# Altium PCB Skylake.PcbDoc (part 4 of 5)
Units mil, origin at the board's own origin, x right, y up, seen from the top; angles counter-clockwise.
Board outline 4000 x 4000 mil, 8 copper layers (TOP LAYER, GND1#2, SIG1#3, SIG2#4, GND2#5, SIG3#6, GND3#7, BOTTOM LAYER), stack 132.6 mil thick; 343 components, 142 nets, 972 pads, 752 vias.
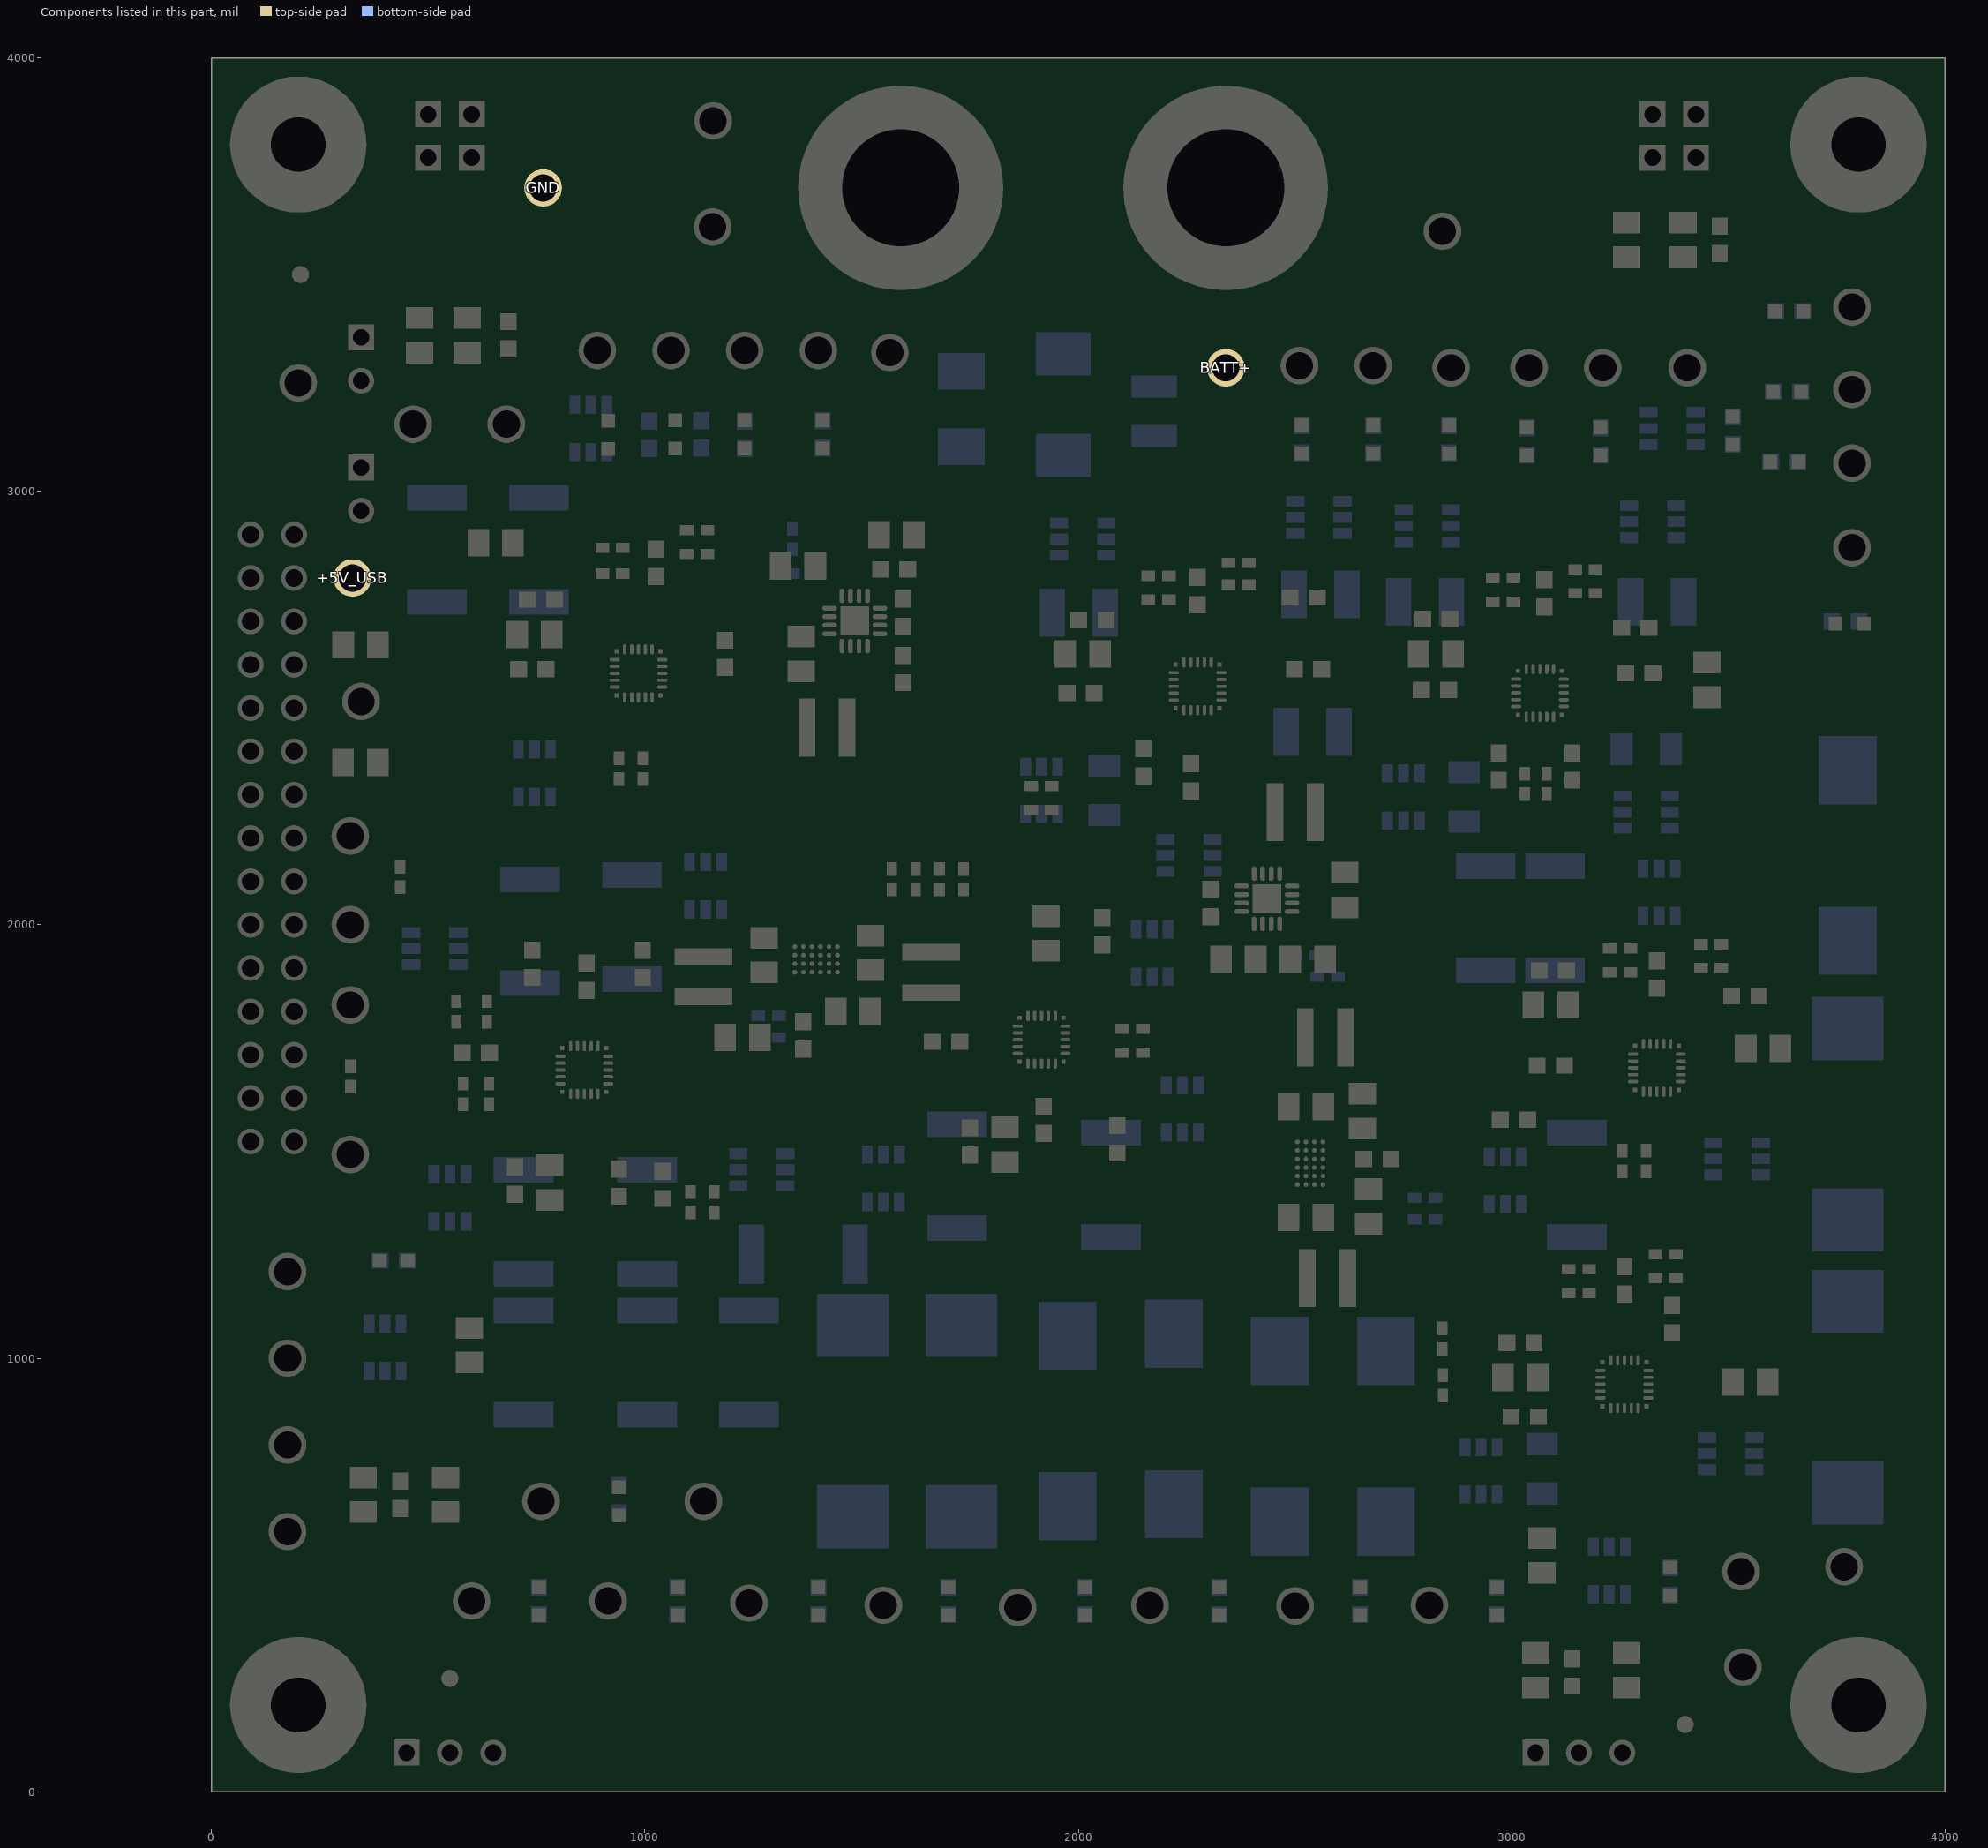
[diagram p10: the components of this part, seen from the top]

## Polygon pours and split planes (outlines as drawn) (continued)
V2(3.3V) on TOP LAYER "Top Layer-No Net" (solid, pour order 239): 832.79,1523.35 832.79,1571.37 847.04,1585.62 876.71,1585.62 888.36,1573.97 888.36,1528.73 877.38,1517.75 838.39,1517.75
V2(3.3V) on TOP LAYER "Top Layer-No Net" (solid, pour order 240): 833,1757.33 833,1805.35 844.85,1817.2 879.32,1817.2 888.57,1807.95 888.57,1762.71 871.39,1745.53 844.8,1745.53
V4(1.00V) on TOP LAYER "Top Layer-No Net" (solid, pour order 242): 1074.32,2605.96 1122.34,2605.96 1132.04,2596.26 1134.19,2594.11 1134.19,2571.71 1134.19,2559.64 1127.73,2553.18 1124.94,2550.39 1090.26,2550.39 1079.7,2550.39 1071.95,2558.14 1068.72,2561.37 1068.72,2588.3 1068.72,2600.36 1074.1,2605.74
GND on TOP LAYER "Top Layer-No Net" (solid, pour order 228): 643.03,2908.98 643.03,2830.71 637.29,2824.97 635.47,2823.16 593.77,2823.16 559.62,2823.16 549.64,2833.13 548.43,2834.34 548.43,2868.19 548.43,2900.82 557.81,2910.19 563.55,2915.93 617.04,2915.93 635.78,2915.93 642.42,2909.28
GND on TOP LAYER "Top Layer-No Net" (solid, pour order 223): 18 vertices, not listed, extent 551.02,924.21 633.29,1015.22
GND on TOP LAYER "Top Layer-No Net" (solid, pour order 222): 18 vertices, not listed, extent 3028.49,438.19 3110.46,530.16
BATT+ on TOP LAYER "Top Layer-No Net" (solid, pour order 269): 17 vertices, not listed, extent 3416.96,2462.19 3488.05,2552.6
BATT+ on TOP LAYER "Top Layer-No Net" (solid, pour order 272): 18 vertices, not listed, extent 3002.52,558.98 3106.08,618.59
BATT+ on TOP LAYER "Top Layer-No Net" (solid, pour order 275): 553.94,1126.76 626.13,1126.76 631.85,1121.04 632.14,1120.75 632.14,1085.09 632.14,1049.98 627,1044.84 626.99,1044.85 568.78,1044.85 555.07,1044.85 548.23,1051.69 547.37,1052.55 547.37,1097.07 547.37,1120.76 553.94,1127.33
BATT+ on TOP LAYER "Top Layer-No Net" (solid, pour order 277): 721.77,2936.69 721.77,2856.99 714.76,2850.93 669.71,2850.93 665,2855 665,2931.98 675.37,2940.93 715.24,2940.93 721.84,2935.24
+5V_USB on TOP LAYER "Top Layer-No Net" (solid, pour order 294): 267.52,2608.49 267.52,2699.62 276.85,2708.95 279.96,2712.06 308.26,2712.06 326.22,2712.06 332.09,2706.19 335.19,2703.09 335.19,2670.63 335.19,2612.96 330.02,2607.79 326.91,2604.68 304.81,2604.68 272.02,2604.68 267.52,2609.18
GND on TOP LAYER "Top Layer-No Net" (solid, pour order 247): 3114.14,2354.14 3157.02,2354.14 3167.2,2343.95 3167.2,2291.84 3161.04,2285.68 3108.95,2285.68 3101.11,2293.52 3101.11,2341.11
V3(3.3V) on TOP LAYER "Top Layer-No Net" (solid, pour order 231): 3479.27,1640.84 3431.25,1640.84 3419.4,1652.69 3419.4,1685.81 3443.79,1710.2 3460.1,1710.2 3484.87,1685.43 3484.87,1646.44
GND on TOP LAYER "Top Layer-No Net" (solid, pour order 256): 3311.06,1947.11 3370.99,1947.11 3377.77,1940.33 3377.77,1900.47 3373.59,1896.29 3321.59,1896.29 3306.36,1911.52 3306.36,1942.41
BATT+ on TOP LAYER "Top Layer-No Net" (solid, pour order 323): 2021.62,2657.78 2092.59,2657.78 2102.19,2648.18 2102.19,2604.85 2089.81,2592.47 2024.47,2592.47 2018.48,2598.46 2018.48,2654.07 2022.48,2658.07
V1.8DX_SENSORS on TOP LAYER "Top Layer-No Net" (solid, pour order 181): 18 vertices, not listed, extent 2039.67,2674.81 2124.66,2753.36
GND on TOP LAYER "Top Layer-No Net" (solid, pour order 303): 2300.95,2330.86 2307.76,2324.05 2307.76,2283.69 2301.44,2277.37 2240.63,2277.37 2232.73,2285.27 2232.73,2322.03 2241.56,2330.86
V1.8M on TOP LAYER "Top Layer-No Net" (solid, pour order 194): 3124.48,2441.33 3172.23,2441.33 3180.81,2432.75 3180.81,2384.42 3172.82,2376.43 3119.21,2376.43 3111.81,2383.83 3111.81,2428.66
V1.8DX_USBSDIO on TOP LAYER "Top Layer-No Net" (solid, pour order 290): 2912.52,2421.33 2913.1,2421.91 2987.65,2421.91 2994.45,2415.11 2994.45,2379.3 2989.34,2374.19 2905.89,2374.19 2895.77,2384.31 2895.77,2404.77 2912.13,2421.13
MODPHY on TOP LAYER "Top Layer-No Net" (solid, pour order 236): 18 vertices, not listed, extent 828.25,2421.24 920.24,2484.65
V3.3M on TOP LAYER "Top Layer-No Net" (solid, pour order 276): 2075.16,1597.69 2128.79,1597.69 2133.76,1592.72 2133.76,1522.86 2128.03,1517.13 2072.09,1517.13 2069.26,1519.96 2069.26,1591.79
GND on TOP LAYER "Top Layer-No Net" (solid, pour order 258): 3047.3,2831.79 3106.52,2831.79 3118.61,2819.7 3118.61,2781.52 3113.71,2776.62 3053.03,2776.62 3044.41,2785.24 3044.41,2828.9
V2(3.3V) on TOP LAYER "Top Layer-No Net" (solid, pour order 237): 1881.76,1601.76 1881.76,1634.58 1902.95,1655.77 1926.54,1655.77 1943.19,1639.12 1943.19,1601.28 1932.21,1590.3 1893.22,1590.3
GND on TOP LAYER "TOP LAYER-No Net 1" (solid, pour order 182): 2249.82,2106 2285.13,2106 2285.13,2067.1 2266,2047.98 2266,1955.53 2311.46,1955.53 2335,1931.99 2344.61,1922.38 2344.61,1852 2265,1852 2262,1855 2232.77,1884.23 2232.77,2088.95
GND on TOP LAYER "Top Layer-No Net" (solid, pour order 195): 34 vertices, not listed, extent 1238.16,1556.47 1576.87,1919.54
GND on TOP LAYER "Top Layer-No Net" (solid, pour order 322): 1996.77,2757.49 2020.44,2733.82 2020.44,2680.38 1994.97,2654.91 1994.97,2399.79 1976.59,2381.41 1873.88,2381.41 1849.29,2406 1849.29,2718.23 1888.55,2757.49
GND on TOP LAYER "Top Layer-No Net" (solid, pour order 191): 1922.01,2280.18 1921.44,2279.61 1921.44,2247.32 1898.98,2224.86 1898.98,2208.79 1905.62,2202.15 1924,2202.15 1931.08,2209.23 1931.08,2224.91 1958.27,2252.1 1958.27,2279.16 1955.81,2281.62 1923.19,2281.62 1921.91,2280.34
GND on TOP LAYER "Top Layer-No Net" (solid, pour order 201): 17 vertices, not listed, extent 3355,3590 3525,3675
GND on TOP LAYER "Top Layer-No Net" (solid, pour order 203): 3220,3685 3320,3685 3335,3670 3335,3610 3320,3595 3220,3595 3205,3610 3205,3670
NetL6_1 on TOP LAYER "Top Layer-No Net" (solid, pour order 184): 1498.99,2659.2 1498.9,2383.33 1489.07,2373.52 1449.64,2373.52 1439.45,2383.68 1439.45,2659.2
GND on TOP LAYER "TOP LAYER-No Net 1" (solid, remove dead copper, pour order 178): 2392.94,2089.53 2493.07,2089.53 2493.07,2067.49 2493.23,2067.22 2390.24,2067.22 2390.24,2086.83
BATT+ on TOP LAYER "Top Layer-No Net" (solid, pour order 198): 40 vertices, not listed, extent 1227.48,1993.09 2631.84,3959.87
BATT+ on BOTTOM LAYER "Top Layer-No Net" (solid, pour order 308): 1383,2892 1445,2892 1460.13,2876.87 1460.13,2814.92 1478.17,2796.88 1478.17,2758.17 1472,2752 1407.7,2752 1370.38,2789.32 1370.38,2879.38
GND on BOTTOM LAYER "Top Layer-No Net" (solid, pour order 314): 2582.59,1877.16 2582.59,1917.43 2593.38,1928.22 2629.29,1928.22 2646.4,1911.11 2646.4,1882.5 2631.23,1867.34 2585,1867.34 2582.59,1869.74 2582.75,1869.91 2582.75,1877.8
V3.3DX_3G4G on BOTTOM LAYER "Top Layer-No Net" (solid, pour order 302): 1663.79,1195.8 1822.55,1195.8 1850,1168.35 1850,996.06 1821.13,967.19 1659.53,967.19 1641,985.72 1641,1174.12 1663.79,1196.91
GND on BOTTOM LAYER "Top Layer-No Net" (solid, pour order 348): 18 vertices, not listed, extent 3024.03,638.88 3151.17,725.24
V3.3DX_3G4G on BOTTOM LAYER "Top Layer-No Net" (solid, pour order 347): 17 vertices, not listed, extent 1953.34,1918.41 2102.16,1999.01
V3.3DX_AUDIO on BOTTOM LAYER "Top Layer-No Net" (solid, pour order 254): 1816.26,1623.41 1816.26,1656.09 1838.84,1678.67 1872.51,1678.67 1882.44,1668.74 1882.44,1617.34 1918.55,1581.23 1918.55,1524.25 1898.62,1504.32 1776.59,1504.32 1766.93,1513.98 1766.93,1574.08
V1.8DX_SSD on BOTTOM LAYER "Top Layer-No Net" (solid, pour order 345): 2350.66,2351.42 2350.65,2351.41 2302.37,2351.41 2282.27,2371.51 2282.27,2391.9 2329.64,2439.27 2355.5,2439.27 2362.65,2432.12 2362.65,2363.11 2350.66,2351.12
V1.8DX_SSD on BOTTOM LAYER "Top Layer-No Net" (solid, pour order 205): 18 vertices, not listed, extent 2280.74,2107.15 2509.45,2528.83
GND on BOTTOM LAYER "Top Layer-No Net" (solid, pour order 343): 3075,1325 3230,1325 3235,1325 3250,1310 3250,1270 3250,1255.51 3239.71,1245.22 3234.49,1240 3155,1240 3080,1240 3070,1250 3070,1305 3070,1320 3075,1325
GND on BOTTOM LAYER "Top Layer-No Net" (solid, pour order 342): 2811.11,1335.99 2857.56,1335.99 2863.98,1329.57 2864.62,1328.93 2864.62,1311.81 2864.62,1298.32 2857.56,1291.26 2849.64,1283.34 2828.45,1283.34 2815.39,1283.34 2811.75,1286.98 2806.19,1292.54 2806.19,1311.59 2806.19,1331.07 2811.11,1335.99
BATT+ on BOTTOM LAYER "Top Layer-No Net" (solid, pour order 341): 2816.04,1413.93 2856.3,1413.93 2861.48,1408.75 2864.54,1405.69 2864.54,1378.14 2864.54,1363.55 2860.77,1359.78 2859.12,1358.13 2834.17,1358.13 2810.87,1358.13 2804.98,1364.02 2804.5,1364.5 2804.5,1377.67 2804.5,1401.92 2816.04,1413.46
V3.3DX_SSD on BOTTOM LAYER "Top Layer-No Net" (solid, pour order 338): 2639.51,1114.55 2793.87,1114.55 2815.52,1092.9 2815.52,941.31 2787.76,913.55 2640.05,913.55 2606.75,946.85 2606.75,1081.79
NetR84_2 on BOTTOM LAYER "Top Layer-No Net" (solid, pour order 305): 3713.14,1412.82 3839.97,1412.82 3862.35,1390.44 3862.35,1066.54 3848.08,1052.27 3700.1,1052.27 3685.13,1067.24 3685.13,1384.81
NetR95_2 on BOTTOM LAYER "Top Layer-No Net" (solid, pour order 330): 18 vertices, not listed, extent 2140,925 2540,1145
GND on BOTTOM LAYER "Top Layer-No Net" (solid, pour order 210): 24 vertices, not listed, extent 1638.97,973.5 2145.42,1481.71
GND on BOTTOM LAYER "Top Layer-No Net" (solid, pour order 326): 26 vertices, not listed, extent 433.69,2465.54 691.23,2804.33
GND on BOTTOM LAYER "Top Layer-No Net" (solid, pour order 324): 1880.12,2787.66 1985.69,2787.66 1995.94,2777.41 1995.94,2521.42 1981.17,2506.65 1899.74,2506.65 1868.43,2537.96 1868.43,2775.97
GND on BOTTOM LAYER "Top Layer-No Net" (solid, pour order 318): 26 vertices, not listed, extent 2849.52,1590.43 3043.35,1941.83
GND on BOTTOM LAYER "Top Layer-No Net" (solid, pour order 313): 17 vertices, not listed, extent 1319.75,2897.23 1367.62,2962.78
NetR58_2 on BOTTOM LAYER "Top Layer-No Net" (solid, pour order 307): 647.39,1233.41 781.27,1233.41 791.66,1223.02 792.27,1222.41 792.27,1213.24 792.27,1059.8 786.77,1054.3 785.55,1053.08 758.65,1053.08 657.17,1053.08 646.78,1063.47 640.66,1069.59 640.66,1122.76 640.66,1227.91 646.16,1233.41
NetR56_2 on BOTTOM LAYER "Top Layer-No Net" (solid, pour order 306): 932.06,1232.43 1067.14,1232.43 1080.15,1219.42 1079.33,1218.6 1079.33,1194.19 1079.33,1060.75 1068.76,1050.18 1067.94,1049.36 1048.41,1049.36 944.26,1049.36 927.99,1065.63 923.11,1070.51 923.11,1151.06 923.11,1222.67 932.06,1231.62
NetR70_2 on BOTTOM LAYER "Top Layer-No Net" (solid, pour order 300): 1407.25,721.32 1800.03,721.32 1816.3,705.05 1817.78,703.57 1817.78,679.16 1817.78,559.33 1813.34,554.89 1811.86,553.41 1763.04,553.41 1402.08,553.41 1387.28,568.21 1385.06,570.43 1385.06,637.74 1385.06,699.87 1406.51,721.32
NetR96_2 on BOTTOM LAYER "Top Layer-No Net" (solid, pour order 298): 1911.5,748.94 2278.62,748.94 2293.79,733.77 2297.04,730.52 2297.04,661.21 2297.04,592.98 2281.88,577.82 2272.13,568.07 2064.2,568.07 1919.09,568.07 1900.67,586.49 1897.42,589.74 1897.42,668.79 1897.42,734.86 1911.5,748.94
NetR94_2 on BOTTOM LAYER "Top Layer-No Net" (solid, pour order 296): 2399.16,715 2770.84,715 2785.14,700.7 2785.14,700.69 2785.14,630.42 2785.14,556.56 2775.61,547.03 2763.7,535.11 2727.95,535.11 2406.32,535.11 2390.82,550.6 2390.82,617.31 2390.82,704.28 2399.16,712.62
NetR82_2 on BOTTOM LAYER "Top Layer-No Net" (solid, pour order 293): 2872,2176.1 3161.77,2176.1 3177.66,2160.21 3177.66,2127.2 3177.66,2105.8 3172.16,2100.3 3166.66,2094.8 2955.75,2094.8 2876.88,2094.8 2864.05,2107.63 2862.21,2109.47 2862.21,2152.26 2862.21,2166.31 2872,2176.1
GND on BOTTOM LAYER "Top Layer-No Net" (solid, pour order 292): 22 vertices, not listed, extent 2848.75,2209.82 2987.3,2310.79
GND on BOTTOM LAYER "Top Layer-No Net" (solid, pour order 289): 3342.83,2451.49 3396.16,2451.49 3402.15,2445.5 3409.57,2438.08 3409.57,2386.76 3409.57,2342.27 3406.43,2339.13 3404.15,2336.85 3394.17,2336.85 3349.1,2336.85 3340.55,2345.4 3340.84,2345.69 3340.84,2374.5 3340.84,2449.79 3342.83,2451.78
V1.8M on BOTTOM LAYER "Top Layer-No Net" (solid, pour order 287): 3157.84,2452.75 3267.48,2452.75 3276.57,2443.66 3279.09,2441.14 3279.09,2393.64 3279.09,2288.55 3276.57,2286.03 3270,2286.03 3206.83,2286.03 3196.23,2296.63 3149.75,2343.11 3149.75,2401.72 3149.75,2444.16 3158.34,2452.75
V1.8DX_AUDIO on BOTTOM LAYER "Top Layer-No Net" (solid, pour order 281): 36 vertices, not listed, extent 2389.95,2701.92 2527.64,2998
V1.8DX_SENSORS on BOTTOM LAYER "Top Layer-No Net" (solid, pour order 274): 18 vertices, not listed, extent 2031.81,2663.7 2121.84,2864.89
GND on BOTTOM LAYER "Top Layer-No Net" (solid, pour order 271): 1986.92,2218.14 1986.92,2270.25 1995.2,2278.53 1998.3,2281.63 2069.39,2281.63 2090.44,2281.63 2095.27,2276.8 2096.31,2275.76 2096.31,2231.94 2096.31,2230.21 2084.93,2218.83 2074.92,2208.82 2001.76,2208.82 1996.93,2208.82 1987.61,2218.14
GND on BOTTOM LAYER "Top Layer-No Net" (solid, pour order 215): 1019.56,2169.64 1047.19,2142.01 1047.19,2086.24 1002.52,2041.57 662.28,2041.57 641.55,2062.3 641.55,2139.41 671.78,2169.64
V3.3DX_SSD on BOTTOM LAYER "Top Layer-No Net" (solid, pour order 229): 26 vertices, not listed, extent 3140.19,806.74 3501.54,1031.7
GND on BOTTOM LAYER "Top Layer-No Net" (solid, pour order 209): 3365.56,2807.44 3442.23,2807.44 3451.72,2797.95 3451.72,2696.48 3443.26,2688.02 3367.38,2688.02 3361.93,2693.47 3362.23,2693.77 3362.23,2804.16 3365.48,2807.41
BATT+ on BOTTOM LAYER "Top Layer-No Net" (solid, pour order 299): 2423.37,1629.72 2487.63,1629.72 2510.06,1607.29 2510.06,1461.9 2509.92,1461.9 2503.33,1455.31 2503.15,1455.13 2414.05,1455.13 2399.84,1469.34 2399.84,1606.19 2423.37,1629.72
BATT+ on BOTTOM LAYER "Top Layer-No Net" (solid, pour order 301): 2427.72,1444.97 2428.16,1444.53 2504.42,1444.53 2504.42,1444.29 2510.08,1438.63 2510.31,1438.4 2510.31,1417.64 2510.31,1293.64 2501.88,1285.21 2430.16,1285.21 2411.99,1303.38 2411.99,1429.24 2427.72,1444.97
V3.3DX_WIFI on BOTTOM LAYER "Top Layer-No Net" (solid, pour order 218): 3394.83,1758.56 3503.66,1758.56 3519.39,1742.83 3519.39,1508.91 3494.92,1484.44 3431.01,1484.44 3384.07,1531.39 3384.07,1747.8
V3.3DX_SSD on BOTTOM LAYER "Top Layer-No Net" (solid, pour order 339): 20 vertices, not listed, extent 2641.34,971.46 3188.08,1185.61
NetR71_2 on BOTTOM LAYER "Top Layer-No Net" (solid, pour order 304): 1385.5,1251.37 1441.48,1307.35 1526.64,1307.35 1574.4,1259.59 1574.4,1007.4 1553.85,986.85 1404.42,986.85 1385.5,1005.77
GND on BOTTOM LAYER "Top Layer-No Net" (solid, pour order 202): 17 vertices, not listed, extent 1159.23,798.87 1326.06,918.37
GND on BOTTOM LAYER "Top Layer-No Net" (solid, pour order 200): 17 vertices, not listed, extent 924.23,798.87 1091.06,918.37
GND on BOTTOM LAYER "Top Layer-No Net" (solid, pour order 199): 17 vertices, not listed, extent 639.23,798.87 806.06,918.37
V4(1.00V) on BOTTOM LAYER "Top Layer-No Net" (solid, pour order 211): 791.85,3118.17 843.19,3118.17 847.91,3113.45 850.49,3110.87 850.49,3094.12 850.49,3058.26 844.47,3052.24 841.89,3049.66 809.25,3049.66 799.59,3049.66 793.14,3056.11 787.13,3062.12 787.13,3106.36 787.13,3113.66 791.85,3118.38
NetR105_2 on BOTTOM LAYER "Top Layer-No Net" (solid, pour order 267): 449.47,3032.95 450.25,3032.28 817.06,3032.28 830.54,3020.84 830.54,2960.99 817.86,2950.23 816.27,2948.88 461.36,2948.88 445.51,2962.34 436,2970.41 436,3021.52 448.68,3032.28
V3.3M on BOTTOM LAYER "Top Layer-No Net" (solid, pour order 219): 17 vertices, not listed, extent 1992.57,1490.51 2144.61,1593.87
V1.8S on BOTTOM LAYER "Top Layer-No Net" (solid, pour order 221): 2011.32,2411.71 2091.19,2411.71 2102.39,2400.51 2102.39,2335.23 2091.45,2324.29 2005.16,2324.29 1995.35,2334.1 1995.35,2395.74
BATT+ on BOTTOM LAYER "Top Layer-No Net" (solid, pour order 309): 2447,2014 2498.33,2014 2518.31,1994.02 2518.31,1855.83 2511.01,1848.53 2454.48,1848.53 2446.8,1856.21 2446.8,1950.83 2440.6,1957.03 2440.6,2007.6
V1.8DX_USBSDIO on BOTTOM LAYER "Top Layer-No Net" (solid, pour order 291): 2843.53,2398.66 2854.13,2409.26 2936.86,2409.26 2948.54,2397.58 2948.54,2339.53 2935.18,2326.17 2934.76,2326.59 2851.69,2326.59 2843.53,2334.75
V3.3DX_TOUCHSCREEN on BOTTOM LAYER "Top Layer-No Net" (solid, pour order 224): 19 vertices, not listed, extent 3057.89,1471.74 3226.08,1599.32
V3.3DX_EDP on BOTTOM LAYER "Top Layer-No Net" (solid, pour order 226): 659.8,1524.88 811.53,1524.88 831.82,1504.59 831.82,1418.54 804.9,1391.62 652.36,1391.62 637.72,1406.26 637.72,1502.8
V3.3DX_AUDIO on BOTTOM LAYER "Top Layer-No Net" (solid, pour order 227): 1649.87,1588.08 1780.93,1588.08 1789.97,1579.04 1789.97,1509.93 1784.36,1504.32 1650.5,1504.32 1639.6,1515.22 1639.6,1577.81
V3.3DX_DPWP on BOTTOM LAYER "Top Layer-No Net" (solid, pour order 230): 18 vertices, not listed, extent 3026.78,1863.25 3202.54,1956.09
V3.3DX_EDP on BOTTOM LAYER "Top Layer-No Net" (solid, pour order 241): 575.42,1512 575.42,1579.68 614.18,1618.44 848.09,1618.44 863.5,1603.03 863.5,1538.47 829.77,1504.74 582.68,1504.74
V3.3DX_USBSDIO on BOTTOM LAYER "Top Layer-No Net" (solid, pour order 244): 922.97,1487.92 922.97,1512.6 894.52,1541.05 894.52,1590.69 902.22,1598.39 1035.72,1598.39 1086.57,1547.54 1086.57,1490.81 1066.86,1471.1 939.79,1471.1
V3.3M on BOTTOM LAYER "Top Layer-No Net" (solid, pour order 248): 1933.35,1643.39 1933.35,1680.91 1951.43,1698.99 1992.49,1698.99 2035.44,1656.04 2123.21,1656.04 2144.61,1634.64 2144.61,1571.21 2131.5,1558.1 2018.64,1558.1
V3.3M on BOTTOM LAYER "Top Layer-No Net" (solid, pour order 251): 2211.52,1541.38 2126.84,1541.38 2126.84,1499.66 2214.95,1499.66 2214.95,1540.76 2214.33,1541.38 2212.15,1541.38
V3.3DX_AUDIO on BOTTOM LAYER "Top Layer-No Net" (solid, pour order 257): 28 vertices, not listed, extent 1574.8,1444.07 1670.35,1555.41
V3.3DX_TOUCHSCREEN on BOTTOM LAYER "Top Layer-No Net" (solid, pour order 260): 27 vertices, not listed, extent 3144.24,1471.74 3304.01,1640.52
V3.3DX_TOUCHSCREEN on BOTTOM LAYER "Top Layer-No Net" (solid, pour order 263): 27 vertices, not listed, extent 3009.49,1436 3107.49,1547.54
V3.3DX_DPWP on BOTTOM LAYER "Top Layer-No Net" (solid, pour order 266): 22 vertices, not listed, extent 3080.19,1670.16 3289.76,1912.81
V3.3DX_DPWP on BOTTOM LAYER "Top Layer-No Net" (solid, pour order 268): 22 vertices, not listed, extent 3132.98,1912.18 3315.14,2041.47
V3.3S on BOTTOM LAYER "Top Layer-No Net" (solid, pour order 270): 24 vertices, not listed, extent 3093.55,755.13 3215.59,912.79
V3.3S on BOTTOM LAYER "Top Layer-No Net" (solid, pour order 273): 17 vertices, not listed, extent 2953.74,769.74 3052.52,830.44
BATT+ on BOTTOM LAYER "Top Layer-No Net" (solid, pour order 295): 1242.46,2028.43 1374.54,2028.43 1390.41,2012.56 1390.41,1951.77 1384.42,1945.78 1234.01,1945.78 1227.48,1952.31 1227.48,2013.45
BATT+ on BOTTOM LAYER "Top Layer-No Net" (solid, pour order 297): 1417.67,2031.34 1549.47,2031.34 1565.42,2015.39 1565.42,1956.12 1560.45,1951.16 1460.59,1951.16 1454.31,1944.88 1404.14,1944.88 1399.87,1949.15 1399.87,2013.54
GND on BOTTOM LAYER "Top Layer-No Net" (solid, pour order 340): 1240.33,1851.85 1297.19,1851.85 1302.18,1846.86 1302.18,1830.65 1277.14,1805.61 1277.14,1779.29 1275,1777.15 1246.75,1777.15 1234.98,1788.92 1234.98,1846.72 1239.9,1851.64
GND on BOTTOM LAYER "Top Layer-No Net" (solid, pour order 282): 2657.2,2521.53 2678.43,2500.3 2678.43,2399.71 2659.29,2380.57 2579.9,2380.57 2561.21,2399.26 2561.21,2515.46 2567.28,2521.53
V1.8DX_3G4G on BOTTOM LAYER "Top Layer-No Net" (solid, pour order 284): 2835.01,2895.74 2917.07,2895.74 2924.79,2888.02 2924.79,2690.32 2913.09,2678.62 2835.02,2678.62 2826.24,2687.4 2826.24,2886.55 2835.02,2895.33
V1.8DX_WIFI on BOTTOM LAYER "Top Layer-No Net" (solid, pour order 286): 21 vertices, not listed, extent 3138.14,2662.94 3304.87,2990.84
BATT+ on BOTTOM LAYER "Top Layer-No Net" (solid, pour order 288): 1663.74,3379.15 1688.34,3403.75 2218.11,3403.75 2250.61,3371.25 2250.61,3229.25 2231.98,3210.62 1694.38,3210.62 1663.74,3241.26
MODPHY on BOTTOM LAYER "Top Layer-No Net" (solid, pour order 225): 33 vertices, not listed, extent 678.07,2204.26 1306.26,2993.54
BATT+ on BOTTOM LAYER "Top Layer-No Net" (solid, pour order 179): 1229.48,1755.33 1273.94,1755.33 1278.83,1750.44 1278.83,1705.15 1287.98,1696 1287.98,1675.17 1280.54,1667.73 1233.11,1667.73 1223.76,1677.08 1223.77,1677.09 1223.77,1749.62
V3.3DX_USBSDIO on BOTTOM LAYER "Top Layer-No Net" (solid, pour order 246): 1236.33,1459.74 1069.67,1459.74 1061.36,1468.05 1061.36,1529.34 1080.53,1548.51 1230.46,1548.51 1242.15,1536.82 1242.15,1465.56
V3.3DX_3G4G on BOTTOM LAYER "Top Layer-No Net" (solid, pour order 233): 1967.95,1998.82 1991.5,1975.27 1991.5,1799.52 1965.55,1773.57 1868.82,1773.57 1834.55,1807.84 1834.55,1908.83 1822.9,1920.48 1736.19,1920.48 1725.07,1931.6 1725.07,1983.41 1740.48,1998.82
GND on BOTTOM LAYER "Top Layer-No Net" (solid, pour order 196): 1677.62,3166.34 2224.34,3166.34 2240.49,3150.19 2240.49,3044.52 2220.68,3024.71 1687.15,3024.71 1663.34,3048.52 1663.34,3152.06
GND on GND1#2 "Top Layer-No Net" (solid, pour order 265): 75,3950 1625,3950 3950,3950 3950,3600 3950,50 3600,50 50,50 50,450 50,3950 75,3950
+5V_USB on SIG1#3 "Top Layer-No Net" (solid, pour order 311): 39 vertices, not listed, extent 40,60 3940,3980
BATT+ on SIG1#3 "Top Layer-No Net" (solid, pour order 310): 1300,3940 1300,3100 1205,3005 475,3005 420,2950 420,1185.4 1065.4,540 3160,540 3520,900 3520,2620 3140,3000 3140,3800 2960,3980 1340,3980
V3(3.3V) on SIG2#4 "Top Layer-No Net" (solid, pour order 214): 22 vertices, not listed, extent 3141.08,389.97 3584.74,950.88
V2(3.3V) on SIG2#4 "Top Layer-No Net" (solid, pour order 216): 418.89,1111.8 419.23,1112.14 419.23,1167.49 733.37,1481.63 733.37,1573.28 759.39,1599.3 872.95,1599.3 896.57,1575.68 896.57,1110.86 839.08,1053.37 476.48,1053.37 419.24,1110.61
V3(3.3V) on SIG2#4 "Top Layer-No Net" (solid, pour order 337): 3232.22,1743.7 3451.76,1743.7 3473.05,1722.41 3473.05,1627.66 3442.58,1597.19 3219.7,1597.19 3195.91,1620.98 3195.91,1707.39
V4(1.00V) on SIG2#4 "Top Layer-No Net" (solid, pour order 333): 18 vertices, not listed, extent 871.28,2512.96 1108.99,2620.83
V1(1.8V) on SIG2#4 "Top Layer-No Net" (solid, pour order 332): 18 vertices, not listed, extent 2135.1,2495.75 2417.03,2609.28
V2(3.3V) on SIG2#4 "Top Layer-No Net" (solid, pour order 335): 1884.81,1887.07 1885.19,1886.69 1974.21,1886.69 1994.09,1866.81 1994.09,1635.5 1967.91,1609.32 1861.28,1609.32 1839.65,1630.95 1839.65,1858.6 1867.36,1886.31 1884.81,1886.31
V1(1.8V) on SIG2#4 "Top Layer-No Net" (solid, pour order 331): 2930.98,2591.32 3251.28,2591.32 3261.34,2581.26 3261.34,2488.51 3252.83,2480 2929.87,2480 2919.78,2490.09 2919.78,2580.12
V2(3.3V) on SIG2#4 "Top Layer-No Net" (solid, pour order 334): 760.89,1779.26 906.5,1779.26 933.76,1752 933.76,1549.31 912.53,1528.08 776.86,1528.08 733.92,1571.02 733.92,1752.29
V3(3.3V) on SIG2#4 "Top Layer-No Net" (solid, pour order 336): 3155.51,981.3 3364.34,981.3 3395.91,949.73 3395.91,912.83 3377.87,894.79 3158.56,894.79 3142.62,910.73 3142.62,968.41
V4(1.00V) on SIG2#4 "Top Layer-No Net" (solid, pour order 208): 17 vertices, not listed, extent 785.61,2592.92 1163.19,3130.93
V3.3DX_WIFI on SIG3#6 "Top Layer-No Net" (solid, pour order 213): 3397.75,1721.38 3428.66,1752.29 3627.88,1752.29 3899.52,1480.65 3899.52,792.77 3859.13,752.38 3688.92,752.38 3636.98,804.31 3636.98,1410.16 3540.96,1506.19 3458.64,1506.19 3442.43,1522.4 3442.43,1577.11 3440.19,1577.11 3397.75,1619.55
V3.3DX_3G4G on SIG3#6 "Top Layer-No Net" (solid, pour order 220): 25 vertices, not listed, extent 1632.31,971.85 2025.28,1867.92
GND on GND2#5 "Top Layer-No Net" (solid, pour order 278): 140,3960 1300,3960 3960,3960 3960,3420 3960,40 3760,40 40,40 40,520 40,3960 140,3960
GND on GND3#7 "Top Layer-No Net" (solid, pour order 280): 180,3960 3960,3960 3960,2880 3960,40 3680,40 40,40 40,820 40,3960 180,3960

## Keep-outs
Keep-Out Layer:
  text ".Layer_Name" at 577,-858.49 h60

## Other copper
TOP LAYER:
  rectangle net GND: 2240,2515 2310,2585
  rectangle net GND: 3030,2500 3100,2570
  region net V3.3DX_SSD: 3306.41,912.32 3339.93,912.32 3388.66,863.59 3503.22,863.59 3503.22,826.18 3397.65,826.18 3319.24,904.59 3306.33,904.59 3304.47,906.45 3304.47,910.37 3306.49,912.39
  region net V3.3DX_SSD: 3305.97,975.52 3327.42,975.52 3337.79,985.89 3337.79,1071.32 3347.03,1080.56 3387.96,1080.56 3394.34,1074.18 3394.34,1024.39 3337.45,967.5 3306.41,967.5 3304.21,969.7 3304.21,973.11
  region net V3.3DX_3G4G: 1942.72,1781.66 1942.72,1796.31 1942.43,1796.6 1942.51,1796.68 1942.51,1817.56 1960.33,1835.38 2018.68,1835.38 2028.66,1845.36 2028.66,1971.06 2035.5,1977.9 2098.24,1977.9 2108.38,1967.76 2108.38,1830.74 2086.68,1809.04 1957.44,1809.04 1950.27,1801.87 1950.27,1782.25 1948.25,1780.23 1943.89,1780.23 1942.56,1781.56
  region net V3.3DX_3G4G: 1879.53,1786.56 1879.36,1786.73 1879.36,1801.87 1874.37,1806.86 1861.49,1806.86 1854.72,1813.63 1854.72,1820.55 1857.3,1823.13 1874.53,1823.13 1887.91,1809.75 1887.91,1786.08 1885.33,1783.5 1882.11,1783.5 1879.37,1786.24
  region net MODPHY: 936.26,2607.58 936.18,2607.5 906.92,2607.5 889.32,2625.1 889.32,2636.93 909.14,2636.93 909.23,2636.84 909.15,2636.76 909.15,2634.12 927.83,2615.44 934.82,2615.44 936.26,2614
  region net V3.3DX_EDP: 645.24,1532.38 677.65,1564.79 755.01,1564.79 790.04,1599.82 823.14,1599.82 828.86,1594.1 828.86,1583.95 776.17,1531.26 736.25,1531.26 719.48,1514.49 719.48,1482.96 708.7,1472.18 658.42,1472.18 645.24,1485.36
  region net V3.3DX_EDP: 649.63,1511.31 652.02,1513.7 705.91,1513.7 719.48,1500.13 719.48,1423.48 712.7,1416.7 653.05,1416.7 645.24,1424.51 645.24,1506.91 650.43,1512.1
  region net GND: 983.8,2353.24 984.04,2353 1044.73,2353 1053.7,2361.97 1071.06,2361.97 1079.09,2353.94 1079.09,2315.03 1073.66,2309.6 987.35,2309.6 977.91,2319.04 977.91,2347.35
  region net GND: 3065.55,2315.3 3070.27,2320.02 3152.2,2320.02 3166.9,2305.32 3166.9,2213.8 3154.1,2201 3075.5,2201 3065.55,2210.95
  region net GND: 3435,1450 3295,1450 3295,1410 3305,1400 3435,1400
  region net +3.3V_USB: 3207.53,1175.2 3172.09,1175.2 3162.87,1165.98 3162.87,1128.95 3174.32,1117.5 3209.19,1117.5 3214.08,1122.39 3214.08,1169.52 3208.23,1175.37
  region net +3.3V_USB: 3280.72,1174.85 3310.49,1174.85 3315.46,1179.82 3315.46,1196.47 3317.41,1198.42 3345.24,1198.42 3347.36,1196.3 3347.36,1163.69 3334.6,1150.93 3285.5,1150.93 3279.66,1156.77 3279.66,1173.96 3280.9,1175.2
  region net GND: 3345.23,1251.76 3344.88,1251.41 3280.91,1251.41 3272.05,1242.55 3272.05,1219.68 3278.6,1213.13 3278.95,1213.48 3304.6,1213.48 3315.17,1224.05 3341.97,1224.05 3347.36,1229.44 3347.36,1251.41 3345.93,1251.41 3345.58,1251.76
  region net +3.3V_USB: 1710.17,1785.4 1744.64,1785.4 1752.57,1777.47 1752.57,1697.5 1740.85,1685.78 1714.31,1685.78 1703.28,1696.81 1703.97,1697.5 1703.97,1779.2
  region net +3.3V_USB: 1054.03,2830.76 1068.76,2816.03 1068.76,2785.33 1059.66,2776.23 984.47,2776.23 974.13,2786.57 974.13,2821.37 983.52,2830.76
  region net +3.3V_USB: 3204.52,1174.34 3205.56,1175.38 3298,1175.38 3306.55,1166.83 3306.55,1130.83 3293.09,1117.37 3209.7,1117.37 3196.75,1130.32 3196.75,1166.84 3204.77,1174.86
  region net +3.3V_USB: 3292.66,1878.47 3371.31,1878.47 3381.03,1868.75 3380.71,1868.43 3380.71,1840.86 3368.8,1828.95 3301.13,1828.95 3286.71,1843.37 3286.71,1872.2 3292.66,1878.15
  region net +3.3V_USB: 618.87,1750.93 654.72,1750.93 665.06,1740.59 665.06,1668.21 655.06,1658.21 625.41,1658.21 614.39,1669.23 614.39,1746.1 618.87,1750.58
  region net +3.3V_USB: 3035.54,2762.71 3102.76,2762.71 3116.16,2749.31 3116.16,2718.28 3105.89,2708.01 3040.09,2708.01 3027.85,2720.25 3027.85,2755.02
  region net +3.3V_USB: 2235.11,2766.14 2238.17,2769.2 2307.39,2769.2 2317.51,2759.08 2317.51,2724.7 2305.27,2712.46 2241.47,2712.46 2228.28,2725.65 2228.28,2759.78 2235.58,2767.08
  region net NetC48_2: 1341.43,1786.37 1341.24,1786.56 1341.24,1828.24 1379.79,1866.79 1379.79,1892.86 1382.74,1895.81 1387.33,1895.81 1390.54,1892.6 1390.54,1884.37 1409.72,1865.19 1409.72,1841.25 1394.29,1825.82 1394.29,1762.82 1386.25,1754.78 1347.14,1754.78 1341.18,1760.74 1341.18,1786.33
  region net NetC74_2: 2576.54,1446.35 2609.79,1479.6 2677.58,1479.6 2680.9,1476.28 2680.9,1439.3 2668.66,1427.06 2604.54,1427.06 2597.63,1433.97 2563.71,1433.97 2559.99,1437.69 2559.99,1443.3 2563.04,1446.35
  region net GND: 2544.69,1385.31 2605.31,1385.31 2636.89,1416.89 2688.5,1416.89 2700.75,1429.14 2700.75,1483.58 2683.31,1501.02 2609.78,1501.02 2599.69,1511.11 2548.26,1511.11 2540.35,1519.02 2540.35,1633.43 2549.36,1642.44 2593.91,1642.44 2593.91,1642.23 2604.62,1631.52 2604.62,1578.38 2623.26,1559.74 2791.68,1559.74 2809,1542.42 2809,1376.26 2797.3,1364.56 2638.88,1364.56 2609.76,1335.44 2609.76,1297.58 2603.61,1291.43 2548.41,1291.43 2540.25,1299.59 2540.25,1380.88
  region net V3.3DX_SENSORS: 887.42,1723.46 887.42,1746.13 900.88,1759.59 912.92,1747.55 912.92,1739.15 896.27,1722.5 896.27,1715.83 893.87,1713.43 889.22,1713.43 887.35,1715.3 887.35,1723.54
  region net V3.3A_EC: 824.16,1713.86 824.16,1725.59 802.43,1747.32 809.06,1753.94 818.53,1753.94 832.54,1739.93 832.54,1714.35 830.28,1712.09 825.93,1712.09
  region net V3.3DX_USBSDIO: 888.34,1617.77 887.57,1617 887.57,1587.87 909.27,1566.17 915.66,1566.17 921.79,1572.3 921.79,1579.47 895.59,1605.67 895.59,1617.4 893.75,1619.24 889.54,1619.24 888.12,1617.82
  region net V3.3DX_EDP: 824.69,1618.14 824.33,1617.78 824.33,1605.57 808.25,1589.49 808.25,1584.12 815.1,1577.27 822.64,1577.27 832.67,1587.3 832.67,1616.09 830.62,1618.14
  region net BATT+: 2442.09,2016.99 2442.22,2017.12 2474.16,2017.12 2514.64,1976.64 2514.64,1861.52 2504.52,1851.4 2458.33,1851.4 2449.01,1860.72 2449.01,1951.23 2440.09,1960.15 2440.09,2014.86 2442.09,2016.86
  region net BATT+: 1384,2920 1443.51,2920 1455.73,2907.78 1455.73,2819.27 1478.78,2796.22 1478.78,2749.87 1475.13,2746.22 1442.11,2746.22 1421.95,2766.38 1391.71,2766.29 1367,2791 1367,2903
  region net GND: 2540.05,1360.49 2540.05,1553.32 2542.29,1555.56 2542.53,1555.32 2547.98,1555.32 2551.13,1552.17 2551.13,1485.92 2551.35,1485.7 2566.65,1485.7 2570.4,1481.95 2570.4,1457.28 2566.44,1453.32 2551.21,1453.32 2551.21,1450.51 2551.27,1450.45 2551.27,1361.65 2549.36,1359.74 2540.82,1359.74 2540.07,1360.49
  region net GND: 1329.56,1914.78 1329.72,1914.94 1459.06,1914.94 1459.06,1907.21 1459.38,1906.89 1457.76,1905.27 1429.58,1905.27 1429.42,1905.43 1429.42,1887.71 1427.01,1885.3 1402.68,1885.3 1399.78,1888.2 1399.78,1905.27 1329.56,1905.27 1329.24,1905.59 1329.24,1914.62
  region net GND: 1455.68,1915 1484,1915 1489.32,1909.68 1489.32,1893 1484.32,1888 1464.32,1888 1449.32,1903 1449.32,1908.64
  region net GND: 1297,1915 1340.94,1915 1345.78,1910.16 1341,1905.38 1339.38,1905.38 1310,1876 1293,1876 1289,1880 1289,1907
  region net GND: 1489,2696 1493,2692 1493,2672 1489,2668 1488.87,2668.13 1416.87,2668.13 1411,2674 1411,2689 1418,2696
  region net GND: 2360,2029 2367,2036 2459,2036 2462,2033 2462,2029 2460,2027 2385,2027 2382,2024 2382,2006 2373,1997 2364,1997 2360,2001
  region net V3.3DX_SSD: 3214.87,978.01 3201.91,978.01 3169.92,1010 3159,1010 3156,1007 3156,990 3179,967 3215,967 3217,969 3217,975.88
  region net V3.3DX_WIFI: 3415.48,1697 3447,1728.52 3447,1789 3460,1802 3515,1802 3527,1814 3527,1853.52 3518.08,1862.44 3438.44,1862.44 3411,1835 3411,1716.57 3400.01,1705.58 3378.38,1705.58 3378.38,1697
  region net V3.3M: 1950.58,1685 1950.58,1676.42 1972,1655 1982,1655 1987,1650 1987,1640 1982,1635 1962,1635 1942,1655 1942,1685
  region net V1.8DX_3G4G: 3003.04,2563.68 3002.78,2563.42 2993.98,2563.42 2977.64,2579.76 2977.64,2583.9 2993.98,2583.9 3009.88,2568 3009.88,2566.5 3006.64,2566.5 3003.3,2563.16
  region net V1.8DX_USBSDIO: 2978.2,2476.72 2978.2,2488.59 2996.61,2507 3003.34,2500.27 3003.34,2490.53 2989.88,2477.07 2977.84,2477.07
  region net V1.8DX_SSD: 2334.08,2514.77 2334.37,2514.48 2339.49,2514.48 2345.21,2508.76 2345.21,2494.14 2347.7,2491.65 2363.35,2491.65 2365.4,2493.7 2364.67,2494.43 2364.67,2502.63 2345.21,2522.09 2333.7,2522.09 2330.12,2518.5
  region net V1.8DX_AUDIO: 2330.59,2585.46 2331.58,2585.46 2346.56,2600.44 2346.56,2612.73 2362.93,2612.73 2364.68,2610.98 2364.68,2600.07 2342.47,2577.86 2333.75,2577.86 2330.12,2581.5 2330.59,2581.97
  region net V1.8DX_SENSORS: 2223.01,2577.86 2206.76,2577.86 2189.35,2595.27 2189.35,2607.42 2208.37,2607.42 2208.81,2606.98 2208.81,2590.59 2213.49,2585.91 2221.69,2585.91 2221.69,2583.3 2219.88,2581.5
  region net V1.8S: 2187.83,2482.74 2187.83,2504.85 2201.48,2518.5 2208.65,2518.5 2210.03,2517.12 2210.03,2485.03 2204.33,2479.33 2191.24,2479.33
  region net MODPHY: 1032.37,2615.04 1032.95,2615.62 1049.63,2615.62 1049.63,2616.06 1053.3,2619.73 1053.3,2642.27 1057.83,2646.8 1073.2,2646.8 1076.56,2643.44 1076.56,2626.01 1057.98,2607.43 1034.71,2607.43 1032.22,2609.92 1032.37,2610.07
  region net MODPHY: 1049.35,2551.7 1064.73,2551.7 1080.73,2535.7 1080.73,2515.02 1077.75,2512.04 1077.61,2512.18 1068.82,2512.18 1047.89,2533.11 1047.89,2550.09 1049.65,2551.85
  region net MODPHY: 890.47,2523.42 890.68,2523.63 890.68,2537.13 905.04,2551.49 905.26,2551.27 919.4,2551.27 921.32,2549.35 921.32,2528.55 912.97,2520.2 894.32,2520.2 890.68,2523.84
  region net NetL1_1: 2419.38,2153.88 2414.23,2159.03 2414.23,2327.71 2421.42,2334.9 2470.35,2334.9 2477.54,2327.71 2477.54,2162.48 2470.64,2155.58 2470.64,2108.27 2465.93,2103.56 2421.97,2103.56 2419.38,2106.15
  region net GND: 2478.13,2112.69 2478.02,2098.93 2464,2090.92 2464,2064.21 2506.34,2064.21 2513.61,2071.48 2532.73,2071.48 2540.72,2063.49 2540.72,1888.57 2545.59,1883.7 2545.95,1884.06 2628.52,1884.06 2641.56,1897.1 2641.56,1949.35 2651.97,1959.76 2673.1,1959.76 2673.1,2065 2590.56,2065 2534.51,2121.05 2486.49,2121.05
  region net GND: 2260.61,2116.82 2375.23,2116.82 2404.01,2091.83 2404,2081 2403.9,2063.87 2327.72,2063.69 2322.88,2058.85 2284.2,2058.85 2274.4,2049.05 2255.5,2049.05 2249.82,2054.73 2249.82,2106.03
  region net GND: 2293.6,1955.32 2293.99,1955.71 2351.36,1955.71 2355.57,1951.5 2355.56,1951.49 2355.56,1861.23 2345.24,1850.91 2301.25,1850.91 2288.63,1863.53 2288.63,1950.58 2293.69,1955.64
  region net BATT+: 1234.08,1945.91 1388.97,1945.91 1390.1,1947.04 1390.1,2012.87 1374.54,2028.43 1242.46,2028.43 1227.48,2013.45 1227.48,1952.31 1233.81,1945.98
  region net BATT+: 1561,1951.48 1460.91,1951.48 1454.43,1945 1401.6,1945 1399.87,1946.73 1399.87,2013.54 1417.67,2031.34 1549.47,2031.34 1565.42,2015.39 1565.42,1956.35 1560.86,1951.79
  region net NetL4_1: 2480.88,1817.86 2544.84,1817.86 2561.98,1800.72 2561.98,1674.86 2545.45,1658.33 2475.25,1658.33 2461.98,1671.6 2461.98,1798.96
  region net NetL5_1: 2554.62,1263.29 2571.58,1246.33 2571.58,1111.07 2558.72,1098.21 2489.28,1098.21 2475.63,1111.86 2475.63,1246.51 2492.41,1263.29
  region net NetL2_1: 1591.24,1924.05 1591.24,1997.4 1609.95,2016.11 1713.44,2016.11 1732.8,1996.75 1732.8,1919.02 1717.57,1903.79 1602.68,1903.79 1591.18,1915.29 1591.18,1923.93
  region net NetL3_1: 1068.31,1907.15 1068.31,1982.19 1083.58,1997.46 1187.07,1997.46 1206.43,1978.1 1206.43,1900.37 1191.2,1885.14 1090.32,1885.14
  region net BATT+: 2423.37,1629.72 2487.63,1629.72 2509.32,1608.03 2509.32,1459.07 2505.38,1455.13 2414.05,1455.13 2399.84,1469.34 2399.84,1606.19
  region net BATT+: 2427.72,1444.97 2505.75,1444.97 2509.93,1440.79 2509.93,1293.26 2501.88,1285.21 2430.16,1285.21 2411.99,1303.38 2411.99,1429.24
  region net BATT+: 2384,1953 2433,1953 2436,1950 2436,1866 2429,1859 2385,1859 2383,1861 2383,1952
  region net +3.3V_USB: 2329.37,2797.1 2327.81,2795.54 2327.81,2774.27 2319.51,2765.97 2297.2,2765.97 2286.56,2755.33 2286.56,2728.08 2294.6,2720.04 2351.94,2720.04 2365.18,2733.28 2365.17,2733.29 2365.17,2795.54 2360.76,2799.95 2331.44,2799.95 2328.85,2797.36
  region net GND: 2321.33,2861.45 2322.88,2863 2358.96,2863 2364.4,2857.56 2364.4,2824.87 2359.98,2820.45 2324.44,2820.45 2314.32,2810.33 2288.63,2810.33 2279.29,2819.67 2279.3,2819.68 2279.3,2847.18 2293.57,2861.45
  region net GND: 2297.3,2554 2295.98,2552.68 2295.98,2547.99 2298.32,2545.65 2298.76,2546.09 2326.21,2546.09 2325.13,2547.17 2325.13,2553.55 2324.68,2554
  region net GND: 3113.07,2539.11 3114.83,2537.35 3114.83,2532.61 3113.29,2531.07 3095.13,2531.07 3092.93,2533.27 3093.04,2533.38 3093.04,2536.03 3093.16,2536.03 3096.24,2539.11
  region net GND: 2254.44,2834.26 2200.7,2834.26 2192.64,2826.2 2192.64,2792.37 2200.25,2784.76 2252.1,2784.76 2258.84,2791.5 2258.84,2830.01 2254.15,2834.7
  region net +3.3V_USB: 2249.99,2768.85 2231.03,2768.85 2223.77,2761.59 2193.82,2761.59 2191.52,2759.29 2191.52,2720.65 2199.71,2712.46 2248.17,2712.46 2258.14,2722.43 2258.14,2761.41 2250.34,2769.21
  region net +3.3V_USB: 3102.76,2762.71 3125.41,2762.71 3130.26,2767.56 3130.26,2777.22 3133.19,2780.15 3159.85,2780.15 3162.63,2777.37 3162.63,2724.22 3146.08,2707.67 3100.68,2707.67 3091.9,2716.45 3091.9,2751.85
  region net GND: 3160.58,2842.1 3106.25,2842.1 3094.09,2829.94 3094.09,2808.42 3095.99,2806.52 3161.02,2806.52 3163.8,2809.3 3163.8,2838.74 3160.58,2841.96
  region net +3.3V_USB: 3039.75,2762.72 3039.61,2762.86 2991.72,2762.86 2985.86,2757 2985.86,2718.64 2994.06,2710.44 3048.69,2710.44 3056.45,2718.2 3056.45,2756.57 3050.01,2763.01 3039.75,2763.01
  region net GND: 3052.05,2831.84 2995.28,2831.84 2987.33,2823.89 2987.33,2784.62 2995.03,2776.92 3053.66,2776.92 3060.84,2784.1 3060.84,2823.05
  region net GND: 1093.64,2941.11 998.95,2941.11 988.05,2930.21 988.05,2887.33 994.72,2880.66 1046.14,2880.66 1057.29,2891.81 1106.86,2891.81 1113.09,2898.04 1113.09,2932.55 1104.28,2941.36 1094.15,2941.36
  region net +3.3V_USB: 1081.87,2873.29 1071.77,2873.29 1060.43,2861.95 1060.43,2843.17 1042.71,2825.45 1042.71,2817.12 1049.62,2810.21 1063.97,2810.21 1082.57,2828.81 1103.31,2828.81 1112.7,2838.2 1112.7,2867.08 1106.32,2873.46 1082.22,2873.46
  region net GND: 945.18,2845.53 932.14,2858.57 932.31,2858.74 932.31,2893.29 941.18,2902.16 1003.89,2902.16 1010.81,2895.24 1010.81,2856.09 1000.25,2845.53
  region net +3.3V_USB: 991.63,2830.62 939.79,2830.62 932.77,2823.6 932.77,2789.5 946.04,2776.23 995.91,2776.23 1004.5,2784.82 1004.5,2818.93 992.22,2831.21
  region net GND: 528.49,1697.72 528.94,1697.27 528.94,1626.73 537.67,1618 593.33,1618 598.28,1622.95 598.28,1699.12 585.54,1711.86 540.97,1711.86 528.47,1699.36
  region net +3.3V_USB: 614.79,1677.66 614.79,1625.78 624.46,1616.11 653.71,1616.11 665.96,1628.36 665.96,1674.37 653.71,1686.62 623.04,1686.62 614.55,1678.13
  region net GND: 528.96,1732.78 528.84,1732.9 528.84,1782.46 540.26,1793.88 586.96,1793.88 599.15,1781.69 599.15,1722.8 590.58,1714.23 538.44,1714.23 528.49,1724.18 528.49,1732.31
  region net +3.3V_USB: 618.63,1794.25 658.26,1794.25 667.1,1785.41 667.1,1734.61 657.54,1725.05 621.5,1725.05 613.3,1733.25 613.3,1788.92
  region net +3.3V_USB: 3387.73,1878.31 3403.3,1893.88 3403.3,1907.09 3416.71,1920.5 3447.18,1920.5 3454.71,1912.97 3454.71,1887.28 3445.98,1878.55 3433.95,1878.55 3384.25,1828.85 3358.42,1828.85 3346.46,1840.81 3346.46,1873.13 3351.64,1878.31
  region net GND: 3447.87,1978.07 3444.33,1981.61 3405.89,1981.61 3385.84,1961.56 3348.58,1961.56 3337.97,1950.95 3337.97,1924.05 3349.51,1912.51 3390.09,1912.51 3412.08,1934.5 3448.87,1934.5 3454.23,1939.86 3454.23,1971.7 3447.39,1978.54
  region net +3.3V_USB: 3258.92,1903.34 3288.02,1903.34 3313.69,1877.67 3313.69,1840.79 3302.13,1829.23 3286.07,1829.23 3256.98,1858.32 3256.98,1901.02 3259.31,1903.35
  region net GND: 3258.42,1963 3258.68,1963.26 3349.34,1963.26 3354.4,1958.2 3354.4,1927.19 3347.34,1920.13 3312.34,1920.13 3302.75,1929.72 3259.34,1929.72 3254.69,1934.37 3254.69,1959.4 3258.28,1962.99
  region net V3.3DX_AUDIO: 1879.76,1688.1 1879.4,1687.74 1879.4,1673.92 1874.51,1669.03 1841.99,1669.03 1839.3,1666.34 1836.86,1666.34 1836.86,1659.01 1845.18,1650.69 1877.8,1650.69 1887.34,1660.23 1887.34,1686.63 1885.02,1688.95 1880.86,1688.95 1879.64,1687.73
  region net V3.3DX_SSD: 3155.97,1005.64 3155.97,1029.03 3160.47,1033.53 3160.48,1033.52 3177,1033.52 3181.96,1028.56 3181.96,992.65 3175.67,986.36 3161.79,986.36 3155.98,992.17 3155.98,1004.7
  region net V3.3DX_WIFI: 3411.3,1593.71 3411.3,1524.7 3427,1509 3467,1509 3482.3,1524.3 3482.3,1574.56 3443.3,1613.56 3443.3,1620.61 3420.97,1642.94 3379.99,1642.94 3378.03,1640.98 3378.03,1636.5 3380.19,1634.34 3394.16,1634.34 3402.91,1625.59 3402.91,1602.1
  text ".Layer_Name" at 577,-858.49 h60
GND1#2:
  pour cut-out: 1327,2559 1393,2559 1393,2522.38 1353.39,2522.38 1353.39,2522.32 1327,2522.32
  pour cut-out: 1159,1707 1159,1773 1291,1773 1291,1707
  pour cut-out: 1414,1767 1414,1833 1546,1833 1546,1767
  pour cut-out: 2637,1416 2703,1416 2703,1284 2637,1284
  pour cut-out: 2622,1636 2688,1636 2688,1504 2622,1504
  pour cut-out: 2582,2146 2648,2146 2648,2014 2582,2014
  pour cut-out: 2566.46,2192.2 2526.39,2192.2 2526.39,2327.38 2566.47,2327.38 2566.47,2192.17
  pour cut-out: 1393.46,2387.2 1353.39,2387.2 1353.39,2522.38 1393.47,2522.38 1393.47,2387.17
  pour cut-out: 2529.17,1393.06 2517.01,1393.06 2517.01,1447.66 2532.9,1447.66 2532.9,1393.02 2529.2,1393.02
  pour cut-out: 2529.03,1452.19 2516.87,1452.19 2516.87,1506.79 2532.76,1506.79 2532.76,1452.15 2529.06,1452.15
  pour cut-out: 1338.13,1925.74 1338.13,1937.91 1392.73,1937.91 1392.73,1922.01 1338.09,1922.01 1338.09,1925.72
  pour cut-out: 1397.6,1925.88 1397.6,1938.04 1452.2,1938.04 1452.2,1922.15 1397.56,1922.15 1397.56,1925.85
  pour cut-out: 2641.28,1117.33 2601.2,1117.33 2601.2,1252.51 2641.28,1252.51 2641.28,1117.3
  pour cut-out: 2636.66,1672.74 2596.59,1672.74 2596.59,1807.92 2636.68,1807.92 2636.68,1672.71
  pour cut-out: 2548.31,1117.57 2508.24,1117.57 2508.24,1252.75 2548.32,1252.75 2548.32,1117.54
  pour cut-out: 2543.39,1672.56 2503.32,1672.56 2503.32,1807.74 2543.4,1807.74 2543.4,1672.53
  pour cut-out: 1592.53,1916.39 1592.53,1956.46 1727.71,1956.46 1727.71,1916.38 1592.5,1916.38
  pour cut-out: 1592.63,1823.28 1592.63,1863.34 1727.81,1863.34 1727.81,1823.26 1592.6,1823.26
  pour cut-out: 1067.2,1813.53 1067.2,1853.61 1202.38,1853.61 1202.38,1813.53 1067.17,1813.53
  pour cut-out: 1066.99,1906.73 1066.99,1946.8 1202.17,1946.8 1202.17,1906.72 1066.96,1906.72
  pour cut-out: 2405.47,2118.07 2404.93,2118.61 2404.93,2330.84 2414.54,2340.45 2472.15,2340.45 2485.82,2326.78 2485.82,2107.9 2475.71,2097.79 2417.56,2097.79 2405.47,2109.88
  pour cut-out: 1457.85,2655.87 1457.85,2612.21 1430.74,2585.1 1430.74,2391.62 1444.99,2377.37 1445.91,2378.29 1492.32,2378.29 1504.73,2390.7 1504.73,2657.72 1498.03,2664.42 1466.13,2664.42 1458.15,2656.44
  pour cut-out: 1327,2691 1393,2691 1393,2559 1327,2559
  text ".Layer_Name" at 578.92,-857.59 h60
